(* Logix 5000 project; controller LINAK_EiP_AOI 1769-L16ER-BB1B rev 36.11; software revision 36.00 *)

TASK MainTask (continuous, watchdog 500 ms) : MainProgram

MODULES
   Local : 1769-L16ER-BB1B (PointIO 0, rev 36.11)
      LA36_EiP : vendor 1538 type 12 code 36 (Ethernet 192.168.1.10, rev 1.4, StandardDataDriven RPI 100 ms)   // LINAK EtherNet/IP Actuator
      Discrete_IO : Embedded (PointIO 1, rev 36.11, Output RPI 20 ms)
END_MODULES

ADD_ON_INSTRUCTION LINAK_EiP_AOI   (* revision 1.0, vendor LINAK A/S *)
// Add On Instructions for LINAK EtherNet/IP Actuators
// Revision note:
// Beta version
VAR_IN_OUT
   Actuator_Assembly_Input_Data : SINT[14]; {required}   // Actuator Feedback
   Actuator_Assembly_Output_Data : SINT[6]; {required}   // Actuator RunCommand
END_VAR
VAR_INPUT
   ConnectionFaulted : BOOL := 1; {required}
   Set_Run_To_Position : REAL; {visible}   // Specifies the target position for the actuator to move to, measured in millimeters (mm).
   Run_To_Position : BOOL; {visible}   // Commands the actuator to move to the position specified in “Set_Run_To_Position”.
   Clear_Error : BOOL; {visible}   // Clears any errors indicated in “Actual_Error_Code” and "Actuator_Error”.
   Run_Out : BOOL; {visible}   // Commands the actuator to extend outward.
   Run_In : BOOL; {visible}   // Commands the actuator to retract inward.
   Stop : BOOL; {visible}   // Commands the actuator to stop movement.
   Recovery_Run_Out : BOOL; {visible}   // Forces the actuator to extend outward, regardless of its current state.
   Recovery_Run_In : BOOL; {visible}   // Forces the actuator to retract inward, regardless of its current state.
   Set_Current : REAL := 251.0; {visible}   // Sets the current limit for the actuator's next movement, measured in amperes (A).
   Set_Speed : REAL := 251.0; {visible}   // Sets the speed for the actuator's next movement, expressed as a percentage (%).
   Set_Soft_Start : REAL := 251.0; {visible}   // Sets the ramp-up time for the actuator's next movement, measured in seconds.
   Set_Soft_Stop : REAL := 251.0; {visible}   // Sets the ramp-down time for the actuator's next movement, measured in seconds.
END_VAR
VAR_OUTPUT
   Actual_Position : REAL; {access Read Only, visible}   // The current position of the actuator, measured in millimeters (mm).
   Actual_Speed : REAL; {access Read Only, visible}   // The current speed of the actuator, measured in millimeters per second (mm/s).
   Actual_Current : REAL; {access Read Only, visible}   // The current electrical draw of the actuator, measured in amperes (A).
   Actual_Status_Flags : INT; {access Read Only, visible}   // Represents the current status flags of the actuator.
   Actual_Error_Code : INT; {access Read Only, visible}   // Represents the current error code of the actuator.
   Actual_AUX_Inputs : INT; {access Read Only, visible}   // Represents the current status of the auxiliary inputs.
   Parallel_Error_Source : DINT; {access Read Only, visible}   // Represents the IP address of the parallel actuator with an error.
   Parallel_Error_Group : INT; {access Read Only, visible}   // Represents the status group of the parallel actuator with an error.
   Parallel_Status_Flags : INT; {access Read Only, visible}   // Represents the current status flags of the parallel actuator with an error.
   Input_Error : BOOL; {access Read Only, visible}   // Indicates if any values in the “RunCommand Area Tags” are outside their acceptable range.
   Actuator_Error : BOOL; {access Read Only, visible}   // Indicates if there is an active error in the actuator.
   Position_Lost : BOOL; {access Read Only, visible}   // Indicates if the actuator is in a position lost state.
   Endstop_In : BOOL; {access Read Only, visible}   // Indicates if the actuator is at its most inward position.
   Endstop_Out : BOOL; {access Read Only, visible}   // Indicates if the actuator is at its most outward position.
   Overcurrent : BOOL; {access Read Only, visible}   // Indicates if the actuator has experienced an overcurrent condition.
   Running_Out : BOOL; {access Read Only, visible}   // Indicates if the actuator is currently moving outward.
   Running_In : BOOL; {access Read Only, visible}   // Indicates if the actuator is currently moving inward.
   Heartbeat_Needed : BOOL; {access Read Only, visible}   // Indicates if the heartbeat signal is not being sent to the actuator.
   Outside_Nominal_Conditions : BOOL; {access Read Only, visible}   // Indicates if the actuator is operating outside nominal conditions.
END_VAR
VAR
   rawCommandPosition : DINT; {access None}
   rawCommandCurrent : DINT; {access None}
   rawCommandSpeed : DINT; {access None}
   rawCommandSoftStart : DINT; {access None}
   rawCommandSoftStop : DINT; {access None}
   rawFeedbackCurrent : INT; {access None}
   rawFeedbackStatusFlags : INT; {access None}
   rawFeedbackPosition : INT; {access None}
   rawFeedbackSpeed : INT; {access None}
   rawFeedbackErrorCode : INT; {access None}
   rawFeedbackAUXInput : INT; {access None}
   rawFeedbackPositionLowByte : INT; {access None}
   rawFeedbackPositionHighByte : INT; {access None}
   rawFeedbackSpeedLowByte : INT; {access None}
   rawFeedbackSpeedHighByte : INT; {access None}
   inputPositionError : BOOL; {access None}
   inputSoftStopError : BOOL; {access None}
   inputSoftStartError : BOOL; {access None}
   inputSpeedError : BOOL; {access None}
   inputCurrentError : BOOL; {access None}
END_VAR

ROUTINE Logic   (* structured text *)
   //---------------------------------------------------------------------------------------------------------------------------------------------
   (**********************************************
   FUNCTION BLOCK:         		LINAK_EIP
   VERSION NUMBER:                 V1.0
   MANUFACTURE:                   	LINAK
   TITLE 							LINAK_EIP_AOI
   **********************************************)
   
   //----------------------------------------CLEAR FLAGS----------------------------------------//
   
   Position_Lost := 0; // Clear Position_Lost
   
   //----------------------------------------Initialize error flags----------------------------------------//
   
   inputPositionError := 0;
   inputCurrentError := 0;
   inputSpeedError := 0;
   inputSoftStartError := 0;
   inputSoftStopError := 0;
   
   
   //----------------------------------------COMMAND DATA----------------------------------------//
   
   
   //--------------------POSITION--------------------//
   
   // Clear Error //
   IF Clear_Error THEN
   	Actuator_Assembly_Output_Data[0] := 0;
   	Actuator_Assembly_Output_Data[1] := 251;
   END_IF;
   
   // Run To Position //
   rawCommandPosition := Set_Run_To_Position * 10;		// 0,1mm/bit
   
   IF rawCommandPosition < 0 THEN
       rawCommandPosition := rawCommandPosition + 65536;
   END_IF;
   
   IF rawCommandPosition > 15000 THEN
       inputPositionError := 1;
   ELSIF (rawCommandPosition <= 15000) AND Run_To_Position AND NOT (Clear_Error OR Stop OR Input_Error) THEN
       Actuator_Assembly_Output_Data[0] := rawCommandPosition MOD 256;         // Low byte
       Actuator_Assembly_Output_Data[1] := (rawCommandPosition / 256) MOD 256; // High byte
   END_IF;
   
   // Run Out //
   IF Run_Out AND NOT Run_To_Position AND NOT (Clear_Error OR Stop OR Input_Error) THEN
   	Actuator_Assembly_Output_Data[0] := 1;
   	Actuator_Assembly_Output_Data[1] := 251;
   END_IF;
   
   // Run In //
   IF Run_In AND NOT Run_To_Position AND NOT (Clear_Error OR Stop OR Input_Error) THEN
   	Actuator_Assembly_Output_Data[0] := 2;
   	Actuator_Assembly_Output_Data[1] := 251;
   END_IF;
   
   // Stop //
   IF Stop THEN
   	Actuator_Assembly_Output_Data[0] := 3;
   	Actuator_Assembly_Output_Data[1] := 251;
   END_IF;
   
   // Recovery Run Out //
   IF Recovery_Run_Out AND (Run_To_Position) AND NOT (Clear_Error OR Stop OR Input_Error) THEN
   	Actuator_Assembly_Output_Data[0] := 4;
   	Actuator_Assembly_Output_Data[1] := 251;
   END_IF;
   
   // Recovery Run In //
   IF Recovery_Run_In AND (Run_To_Position) AND NOT (Clear_Error OR Stop OR Input_Error) THEN
   	Actuator_Assembly_Output_Data[0] := 5;
   	Actuator_Assembly_Output_Data[1] := 251;
   END_IF;
   
   
   //--------------------CURRENT--------------------//
   
   rawCommandCurrent := Set_Current * 4;			// 0,25A/bit
   IF rawCommandCurrent < 0 THEN
   	rawCommandCurrent := rawCommandCurrent + 65536;
   END_IF;
   
   IF rawCommandCurrent > 251 THEN
   	IF rawCommandCurrent = 1004 THEN
   		Actuator_Assembly_Output_Data[2] := 251;	// Default value
   	ELSE
   		inputCurrentError := 1;
   	END_IF;
   
   ELSIF rawCommandCurrent <= 250 THEN
   	Actuator_Assembly_Output_Data[2] := rawCommandCurrent;
   END_IF;
   
   
   //--------------------SPEED--------------------//
   
   rawCommandSpeed := Set_Speed * 2;				// 0,5%/bit
   IF rawCommandSpeed < 0 THEN
   	rawCommandSpeed := rawCommandSpeed + 65536;
   END_IF;
   
   IF rawCommandSpeed > 251 THEN
   	IF rawCommandSpeed = 502 THEN
   		Actuator_Assembly_Output_Data[3] := 251;	// Default value
   	ELSE
   		inputSpeedError := 1;
   	END_IF;
   
   ELSIF rawCommandSpeed <= 250 THEN
   	Actuator_Assembly_Output_Data[3] := rawCommandSpeed;
   END_IF;
   
   
   //--------------------SOFT START--------------------//
   
   rawCommandSoftStart := Set_Soft_Start * 20;		// 0,05s/bit
   IF rawCommandSoftStart < 0 THEN
   	rawCommandSoftStart := rawCommandSoftStart + 65536;
   END_IF;
   
   IF rawCommandSoftStart > 251 THEN
   	IF rawCommandSoftStart = 5020 THEN
   		Actuator_Assembly_Output_Data[4] := 251;	// Default value
   	ELSE
   		inputSoftStartError := 1;
   	END_IF;
   
   ELSIF rawCommandSoftStart <= 250 THEN
   	Actuator_Assembly_Output_Data[4] := rawCommandSoftStart;
   END_IF;
   
   
   //--------------------SOFT STOP--------------------//
   
   rawCommandSoftStop := Set_Soft_Stop * 20;		// 0,05s/bit
   IF rawCommandSoftStop < 0 THEN
   	rawCommandSoftStop := rawCommandSoftStop + 65536;
   END_IF;
   
   IF rawCommandSoftStop > 251 THEN
   	IF rawCommandSoftStop = 5020 THEN
   		Actuator_Assembly_Output_Data[5] := 251;	// Default value
   	ELSE
   		inputSoftStopError := 1;
   	END_IF;
   
   ELSIF rawCommandSoftStop <= 250 THEN
   	Actuator_Assembly_Output_Data[5] := rawCommandSoftStop;
   END_IF;
   
   
   //--------------------INPUT ERROR--------------------//
   
   Input_Error := inputPositionError OR inputCurrentError OR inputSpeedError OR inputSoftStartError OR inputSoftStopError;
   
   
   //----------------------------------------FEEDBACK DATA----------------------------------------//
   
   
   //--------------------POSITION--------------------//
   
   rawFeedbackPositionLowByte := Actuator_Assembly_Input_Data[0];
   rawFeedbackPositionHighByte := Actuator_Assembly_Input_Data[1];
   
   IF rawFeedbackPositionLowByte < 0 THEN
       rawFeedbackPositionLowByte := rawFeedbackPositionLowByte + 256;
   END_IF;
   
   IF rawFeedbackPositionHighByte < 0 THEN
       rawFeedbackPositionHighByte := rawFeedbackPositionHighByte + 256;
   END_IF;
   rawFeedbackPosition := (rawFeedbackPositionHighByte * 256) + rawFeedbackPositionLowByte;
   
   IF rawFeedbackPosition < 64256 THEN
   	Actual_Position := rawFeedbackPosition / 10;	// 0,1mm/bit
   ELSIF rawFeedbackPosition = 65024 THEN
   	Position_Lost := 1;
   END_IF;
   
   
   //--------------------CURRENT--------------------//
   
   rawFeedbackCurrent := Actuator_Assembly_Input_Data[2];
   IF rawFeedbackCurrent < 0 THEN
       rawFeedbackCurrent := rawFeedbackCurrent + 256;
   END_IF;
   
   IF rawFeedbackCurrent < 251 THEN
   	Actual_Current := rawFeedbackCurrent / 4;		// 0,25A/bit
   ELSE
   	Actual_Current := 0;
   END_IF;
   
   
   //--------------------STATUS FLAGS--------------------//
   
   rawFeedbackStatusFlags := Actuator_Assembly_Input_Data[3];
   
   IF rawFeedbackStatusFlags < 0 THEN
       rawFeedbackStatusFlags := rawFeedbackStatusFlags + 256;
   END_IF;
   
   Actual_Status_Flags := rawFeedbackStatusFlags;
   
   Endstop_In  				:= (Actuator_Assembly_Input_Data[3] AND 2#00000001) <> 0; // Bit 0
   Endstop_Out  				:= (Actuator_Assembly_Input_Data[3] AND 2#00000010) <> 0; // Bit 1
   Overcurrent  				:= (Actuator_Assembly_Input_Data[3] AND 2#00000100) <> 0; // Bit 2
   Running_Out   				:= (Actuator_Assembly_Input_Data[3] AND 2#00001000) <> 0; // Bit 3
   Running_In  				:= (Actuator_Assembly_Input_Data[3] AND 2#00010000) <> 0; // Bit 4
   Heartbeat_Needed  			:= (Actuator_Assembly_Input_Data[3] AND 2#00100000) <> 0; // Bit 5
   Outside_Nominal_Conditions	:= (Actuator_Assembly_Input_Data[3] AND 2#01000000) <> 0; // Bit 6
   //Reserved  				:= (Actuator_Assembly_Input_Data[3] AND 2#10000000) <> 0; // Bit 7
   
   
   //--------------------ERROR CODE--------------------//
   
   rawFeedbackErrorCode := Actuator_Assembly_Input_Data[4];
   
   IF rawFeedbackErrorCode < 0 THEN
       rawFeedbackErrorCode := rawFeedbackErrorCode + 256;
   END_IF;
   
   Actual_Error_Code := rawFeedbackErrorCode;
   
   IF rawFeedbackErrorCode > 0 THEN
   	Actuator_Error := 1;
   ELSE
   	Actuator_Error := 0;
   END_IF;
   
   
   //--------------------SPEED--------------------//
   rawFeedbackSpeedLowByte := Actuator_Assembly_Input_Data[5];
   rawFeedbackSpeedHighByte := Actuator_Assembly_Input_Data[6];
   
   IF rawFeedbackSpeedLowByte < 0 THEN
       rawFeedbackSpeedLowByte := rawFeedbackSpeedLowByte + 256;
   END_IF;
   
   IF rawFeedbackSpeedHighByte < 0 THEN
       rawFeedbackSpeedHighByte := rawFeedbackSpeedHighByte + 256;
   END_IF;
   rawFeedbackSpeed := (rawFeedbackSpeedHighByte * 256) + rawFeedbackSpeedLowByte;
   
   IF rawFeedbackSpeed < 4016 THEN
   	Actual_Speed := rawFeedbackSpeed / 10;		// 0,1mm/bit
   ELSE
   	Actual_Speed := 0;
   END_IF;
   
   
   //--------------------AUX INPUT--------------------//
   
   rawFeedbackAUXInput := Actuator_Assembly_Input_Data[7];
   
   IF rawFeedbackAUXInput < 0 THEN
       rawFeedbackAUXInput := rawFeedbackAUXInput + 256;
   END_IF;
   
   Actual_AUX_Inputs := rawFeedbackAUXInput;
END_ROUTINE
END_ADD_ON_INSTRUCTION

VAR_GLOBAL   (* controller tags *)
   LA36_EiP_Read_Current_Limit_Out : INT;   // Read LINAK EtherNet/IP Current Limit Out Parameter
   LA36_EiP_Write_Current_Limit_Out : INT;   // Write LINAK EtherNet/IP Current Limit Out Parameter
   LINAK_EiP_LA36_AOI_DB : LINAK_EiP_AOI := (ConnectionFaulted := 1, Set_Current := 251.0, Set_Speed := 251.0, Set_Soft_Start := 251.0, Set_Soft_Stop := 251.0);   // LINAK EtherNet/IP AOI DataBlock
   Read_Parameter : BOOL;
   Read_Parameter_MSG : MESSAGE;   // Read LINAK EtherNet/IP Parameter
        MessageParameters(ServiceCode := 16#000e, DestinationTag := LA36_EiP_Read_Current_Limit_Out, ...)
   Write_Parameter : BOOL;
   Write_Parameter_MSG : MESSAGE;   // Write LINAK EtherNet/IP Parameter
        MessageParameters(ServiceCode := 16#0010, LocalElement := LA36_EiP_Write_Current_Limit_Out, ...)
END_VAR

PROGRAM MainProgram   (* main routine LINAK_EiP_Routine *)

ROUTINE LINAK_EiP_Routine   (* ladder *)
// LINAK EtherNet/IP AOI Routine
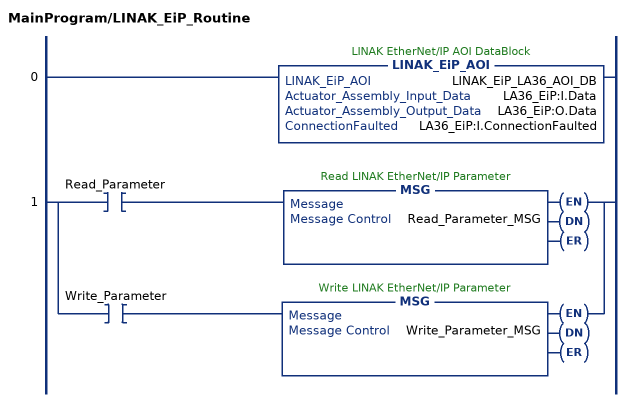
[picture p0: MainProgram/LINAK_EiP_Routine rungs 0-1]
   0: LINAK_EiP_AOI(LINAK_EiP_LA36_AOI_DB,LA36_EiP:I.Data,LA36_EiP:O.Data,LA36_EiP:I.ConnectionFaulted);
   1: [XIC(Read_Parameter) MSG(Read_Parameter_MSG) ,XIC(Write_Parameter) MSG(Write_Parameter_MSG) ];
END_ROUTINE
END_PROGRAM
